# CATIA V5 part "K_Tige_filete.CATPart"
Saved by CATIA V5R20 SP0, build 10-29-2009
Part number: reglage_filete
Bounding box of the stored display mesh (mm): x -5 to 5, y 0 to 155, z -5 to 5
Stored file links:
  G:\Khaled_CFAO_2011\SIL\SIL_GR1\mroland\Khaled\CAD_CATIA_Modifie\K_Tige_filete.CATPart
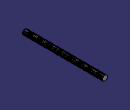
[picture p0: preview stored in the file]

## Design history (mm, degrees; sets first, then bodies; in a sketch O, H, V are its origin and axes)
Set1
  Sketch1 on zx-plane, origin (0, 0, 0), H (-1, 0, 0), V (0, 0, 1)
    circle A1 centre (0, 0) radius 5
    distance O A1 = 5 {= 5mm}
  Point1: type OnCurve, Support edge [face of Pad1 from Sketch1.A1 | end face of Pad1], RefPoint {extremum Reference edge [face of Pad1 from Sketch1.A1 | end face of Pad1], Direction (1, 2, 3)}, Length 17.402
  Point2: type Center, Curve edge [face of Pad1 from Sketch1.A1 | end face of Pad1]
  Line1: type Normal, RefPoint Point2, RefSkin end face of Pad1, Start 0, End 20
  Helix1: Direction Line1, RefPoint Point1, Pitch 1.55, Height 155, TaperAngle 0
  Point3: (0, 0, 0), relative to vertex of Helix1
  Line2: type Tangency, RefPoint Point3, Curve edge [start face of Pad1 | face of Pad1 from Sketch1.A1], Start 0, End 20
  Plane1: type Normal, Curve Line2, RefPoint Point3
  Sketch2 on Plane1, origin (0, 0, 0), H (0, -1, 0), V (0.6136, 0, 0.7897)
    circle A1 centre (0, -5) radius 0.725
    point P1 (0, -5)
    reference projected point E1 (0, -5) from Point3
    distance P1 E1 = 0
    radius A1 = 0.725
  Sweep1: type Unspec, Profile Sketch2, Guide Helix1
Body1 (main body)
  Pad1: profile Sketch1, direction (0, 1, 0), length 155
  Body2
    CloseSurface1: CloseElement Sweep1
  Remove1: tool Body2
